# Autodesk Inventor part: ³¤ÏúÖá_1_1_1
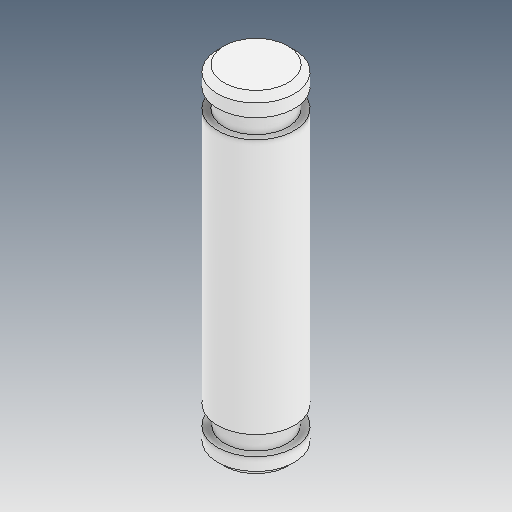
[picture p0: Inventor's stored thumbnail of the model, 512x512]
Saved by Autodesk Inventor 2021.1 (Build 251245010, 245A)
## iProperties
Created: 2021-05
Part Number: ³¤ÏúÖá_1_1_1
Material: Ogólny
Document SubType Name: Modeling
Designer: user
Density: 1 g/cm^3
Appearance: Domyślna
Author: user
Revision Number: ÈÎºÎ
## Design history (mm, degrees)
feature "ÊäÈë1"
node "Bryła1"
